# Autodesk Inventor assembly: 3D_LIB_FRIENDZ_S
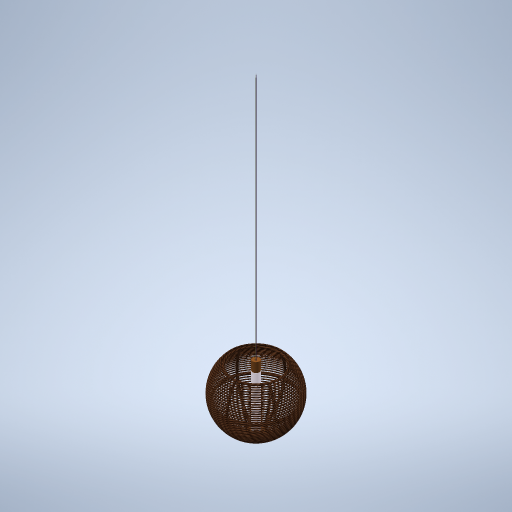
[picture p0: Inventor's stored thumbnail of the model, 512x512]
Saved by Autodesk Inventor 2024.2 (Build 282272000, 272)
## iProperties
Manager: Filip
Company: DARK
Created: 2023-07
Part Number: 3D_LIB_FRIENDZ_S
Document SubType Name: Assembly
Designer: Manuel
Engineer: Filip
Author: Manuel
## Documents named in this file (7)
- C:\Users\Stage\Desktop\Stage Karsten\armatures\Friendz\SPW1069_KARSTEN\3D_LIB_FRIENDZ_S.iam
- C:\Users\Stage\Downloads\SPW1069 - FRIENDS\SPW1069-30.iam
- C:\Users\Stage\Downloads\SPW1069 - FRIENDS\351-201.ipt
- C:\Users\Stage\Downloads\SPW1069 - FRIENDS\SPW1069-002.ipt
- C:\Users\Stage\Downloads\SPW1069 - FRIENDS\5P-Transparant.ipt
- C:\Users\Stage\Desktop\TUUR\2D en 3D\PLANETZZZ PLUZ\PLANETZZZ PLUZ\120-4000-000058.ipt
- C:\Users\Stage\Downloads\SPW1069 - FRIENDS\225-660.iam
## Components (9 placed, 6 different names)
1. SPW1069-30:1 [sub-assembly] — Angle:1, Mate:1, Tangent:1, Angle:2, Mate:2, Mate:3, Mate:4
2. 351-201:1 — Angle:1, Mate:1, Tangent:1, Tangent:2
3. SPW1069-002:1 — Angle:2, Mate:2, Tangent:2
4. 5P-Transparant:1
5. 2273-202:1 — Flush:3, Mate:8
6. 2273-202:2 — Flush:2, Flush:3, Mate:9
7. 2273-202:3 — Flush:1, Flush:2, Mate:6, Mate:7
8. 2273-202:4 — Flush:1, Mate:10
9. 225-660:1 [sub-assembly] — Mate:11, Mate:12
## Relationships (18: Mate 11, Flush 3, Angle 2, Tangent 2)
- Angle:1: SPW1069-30:1 ↔ 351-201:1
- Mate:1: SPW1069-30:1 ↔ 351-201:1
- Tangent:1: SPW1069-30:1 ↔ 351-201:1
- Angle:2: SPW1069-30:1 ↔ SPW1069-002:1
- Mate:2: SPW1069-30:1 ↔ SPW1069-002:1
- Tangent:2: 351-201:1 ↔ SPW1069-002:1
- Mate:3: SPW1069-30:1
- Mate:4: SPW1069-30:1
- Flush:1: 2273-202:3 ↔ 2273-202:4
- Flush:2: 2273-202:2 ↔ 2273-202:3
- Flush:3: 2273-202:1 ↔ 2273-202:2
- Mate:6: 2273-202:3
- Mate:7: 2273-202:3
- Mate:8: 2273-202:1
- Mate:9: 2273-202:2
- Mate:10: 2273-202:4
- Mate:11: 225-660:1
- Mate:12: 225-660:1
